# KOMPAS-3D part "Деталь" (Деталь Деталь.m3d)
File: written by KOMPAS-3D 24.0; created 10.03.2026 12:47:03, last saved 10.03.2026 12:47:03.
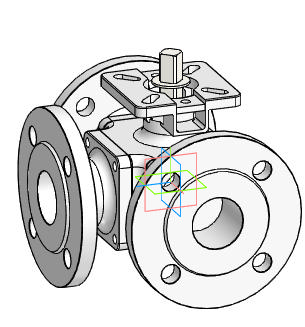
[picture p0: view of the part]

Document properties: Автор: R2D2; Полное имя файла: E:\Работа\Зайцев\BV3232P(4pc)-FP-3WL-F-ISO-H Кран шаровой DN.ru Ду15-100 Ру16\DN50\исходные материалы\Деталь Деталь.m3d

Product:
- Body: Твердое тело1  | qty 1
- Part/product: Деталь
    additional columns: Типовые

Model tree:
1. Твердое тело1  (labels: Твердое тело1)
